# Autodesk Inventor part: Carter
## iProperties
Shininess: 64.0
Length Units: 11269
Angle Units: 11279
Time Units: 11290
Mass Units: 11283
Length Display Precision: 3
Angle Display Precision: 2
Compacted: True
Part Number: Carter
Document SubType Name: Modeling
Created: 2005-01
Material: Par défaut
Designer: Flavien MARTY
Density: 0.0
Volumn: 0.0
Area: 0.0
PropertySet Name: Model Information
Control State: 0
Master: False
Checked Out: False
Norme de conversion: STEP AP203
Nom du fichier: Carter.STEP
Préprocesseur: SolidWorks 2001039
Postprocesseur: Build: Release: 6 RTM Build: 90b - Date: Tue 09/24/2002
Unités envoyées: MILLIMETERS
Incertitude: 0.0
Author: Flavien MARTY
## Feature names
1. 蠆䓽䇤
2. 蠆䓽䇤
3. Base1
